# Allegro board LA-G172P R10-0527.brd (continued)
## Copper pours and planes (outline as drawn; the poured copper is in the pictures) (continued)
CPU_B+ on TOP: 99.74,37.64 100.38,37.01 102.28,37.01 102.36,36.93 102.36,36.73 102.48,36.6 104.49,36.6 104.72,36.37 105.33,36.37 105.48,36.22 105.48,35.46 105.38,35.36 104.79,35.36 104.69,35.46 104.69,35.69 104.24,36.14 100.38,36.14 100.15,35.91 100.15,35.56 99.99,35.41 98.09,35.41 98.08,35.39 97.97,35.39 97.89,35.3 97.89,33.78 97.58,33.48 97.58,30.48 97.48,30.38 94.66,30.38 94.53,30.25 94.53,28.88 94.61,28.8 97.35,28.8 97.77,28.38 99.85,28.38 100.38,27.86 100.4,27.89 102.13,27.89 102.31,27.71 102.31,27.56 102.46,27.41 104.49,27.41 104.72,27.18 105.33,27.18 105.35,27.15 105.35,26.42 105.33,26.39 104.79,26.39 104.21,26.97 100.43,26.97 100.17,26.72 100.17,26.34 100.05,26.21 98.01,26.21 97.89,26.08 97.89,24.56 97.73,24.41 97.73,21.56 97.58,21.41 94.36,21.41 93.77,21.99 93.77,24.8 92.22,26.35 92.22,37.82 92.54,38.14 97.03,38.14 97.52,37.64
CPU_B+ on VCC: 100.45,41.12 100.81,40.76 100.81,37.33 101.59,36.55 104.89,36.55 105.38,36.06 105.38,26.62 105.27,26.52 101.59,26.52 100.93,25.86 100.93,21.92 100.45,21.44 92.94,21.44 92.55,21.82 92.55,40.63 93.04,41.12
HPOUT-L on TOP (solid shape): 32.04,21.06 32.04,20.5 31.47,19.92 31.47,18.9 31.4,18.83 31.27,18.83 31.21,18.9 31.21,20.06 31.66,20.51 31.66,21.06 31.7,21.09 32,21.09
HPOUT-R on TOP (solid shape): 32.61,20.99 32.61,20.48 31.85,19.72 31.85,18.9 31.78,18.83 31.66,18.83 31.59,18.9 31.59,19.89 32.23,20.52 32.23,21.02 32.24,21.04 32.56,21.04
JUSBC1_GND on TOP (solid shape): 10.99,56.68 10.99,55.75 11.27,55.47 11.27,54.71 11.15,54.58 9.88,54.58 9.75,54.71 9.75,55.2 9.53,55.42 8.93,55.42 8.71,55.64 8.71,56.32 8.91,56.52 9.53,56.52 9.75,56.74 9.75,56.74 9.88,56.87 10.8,56.87
JUSBC1_GND on IN3 (solid shape): outline of 695 points within 1.24,55.73 11.15,69.7
JUSBC2_GND on TOP (solid shape): 288.01,67.14 288.01,65.06 287.75,64.81 285.47,64.81 285.41,64.86 285.41,66.74 285.97,67.3 287.84,67.3
JUSBC2_GND on IN3: 282.45,69.22 281.69,69.22 281.08,69.82 281.08,78.78 283.62,81.32 287,81.32 287.9,81.13 288.8,81.32 291.29,81.32 291.59,81.02 291.59,79.15 291.21,78.77 287.1,78.77 287.03,78.91 286.93,79.03 286.28,79.12 285.93,78.57 285.93,69.13 286.43,68.54 287.1,68.93 290.86,68.93 291.05,68.74 291.05,67.85 290.61,67.41 289.72,67.41 288.51,66.2 285.47,66.2
LX1_VCCIN on TOP (solid shape): 109.19,42.59 109.19,40.89 108.99,40.69 108.99,35.33 108.83,35.18 107.51,35.18 106.19,33.86 106.19,33.3 105.96,33.07 105.23,33.07 105.1,33.2 105.1,34.21 105.18,34.29 105.46,34.29 105.58,34.42 105.58,36.32 105.43,36.47 104.79,36.47 104.64,36.63 104.64,36.65 104.62,36.68 102.59,36.68 102.48,36.78 102.48,38.68 102.69,38.89 104.95,38.89 105.3,39.24 107.64,39.24 107.82,39.42 107.82,42.59 108,42.77 109.01,42.77
LX2_VCCIN on TOP (solid shape): 108.8,30.9 108.8,26.88 108.8,26.87 108.8,26.23 107.62,25.05 107.62,21.93 107.3,21.61 106.76,21.61 105.95,22.43 104.52,22.43 104.16,22.78 104.16,23.8 104.41,24.05 105.23,24.05 105.47,24.29 105.47,26.29 105.47,26.29 105.47,27.19 105.37,27.29 104.76,27.29 104.57,27.48 104.56,27.48 104.53,27.51 102.53,27.51 102.41,27.63 102.41,28 102.41,29.49 102.48,29.56 103.82,29.56 103.86,29.56 105.59,31.3 108.4,31.3
LX_0.6V on TOP: 78.18,71.65 78.26,71.74 79.95,71.74 80.18,71.51 80.18,69.37 80.72,68.83 81.66,68.83 81.76,68.73 81.76,68.53 81.71,68.48 80.03,68.48 79.47,67.92 79.47,66.58 79.41,66.52 78.9,66.52 78.84,66.58 78.84,67.18 78.65,67.37 78.34,67.37 78.18,67.53
LX_1.1V on TOP (solid shape): 101.7,64.13 101.7,62.61 102.09,62.22 102.09,59.84 101.94,59.69 98.19,59.69 97.68,60.2 97.68,60.2 97.61,60.27 95.26,60.27 95.11,60.42 95.11,61.28 95.22,61.39 97.48,61.39 98.58,62.49 99.66,62.49 99.71,62.55 99.71,63.22 99.82,63.32 100.45,63.32 100.6,63.47 100.6,64.11 100.65,64.16 101.67,64.16
LX_1.8V on TOP (solid shape): 208.99,25.6 208.99,23.93 209.37,23.54 209.37,21.92 209.52,21.77 209.91,21.77 209.96,21.71 210.61,21.71 210.66,21.66 210.66,21.46 210.64,21.44 210.14,21.44 210.06,21.36 208.93,21.36 207.85,20.28 207.31,20.28 207.11,20.07 207.11,19.16 207.02,19.08 206.39,19.08 206.22,19.25 206.22,20.51 205.94,20.79 205.94,23.86 206,23.93 207.92,23.93 208.08,24.09 208.08,25.59 208.12,25.62 208.96,25.62
LX_3V on TOP (solid shape): 81.76,57.5 81.76,56.64 81.83,56.56 81.83,55.04 82.15,54.72 82.15,53.86 82.67,53.34 83.24,53.34 84,52.58 85.41,52.58 85.57,52.42 85.57,50.7 85.49,50.62 84.48,50.62 82.97,49.11 80.07,49.11 79.84,49.35 79.84,55.08 80.46,55.7 80.49,55.7 80.59,55.8 80.59,56.08 81.15,56.64 81.21,56.64 81.24,56.67 81.27,56.67 81.38,56.77 81.38,56.8 81.39,56.81 81.39,57.52 81.43,57.55 81.71,57.55
LX_5V on TOP (solid shape): 22.7,7.47 23.59,7.47 23.72,7.34 23.72,7.21 23.55,7.05 23.04,7.05 22.96,6.97 21.32,6.97 20.67,6.32 20.67,3.53 20.54,3.4 19.97,3.4 19.78,3.21 19.78,2.51 19.72,2.45 18.19,2.45 18.13,2.51 18.13,4.29 17.75,4.67 16.23,4.67 15.97,4.93 15.97,7.53 16.32,7.88 18.92,7.88 19.34,8.29 21.88,8.29
LX_5VB on TOP (solid shape): 275.5,8.42 275.5,3.08 275.24,2.83 274.15,2.83 273.37,2.05 272.51,2.05 272.18,2.38 272.18,2.84 271.56,3.47 271.56,4.33 270.76,5.13 269.49,5.13 269.44,5.18 269.44,5.48 269.54,5.59 270.18,5.59 270.73,5.59 271.98,5.59 272,5.59 272.23,5.82 272.23,5.84 272.28,5.89 272.28,7.49 272.38,7.59 273.27,7.59 273.97,8.29 273.97,8.42 274.1,8.55 275.37,8.55
LX_AUX on TOP (solid shape): 147.58,12.79 147.58,7.66 146.46,6.54 146.46,4.32 146.32,4.17 145.74,4.17 145.51,4.4 145.51,6.66 145.24,6.93 144.5,6.93 144.44,6.98 144.44,7.73 144.44,7.73 144.44,9.23 144.13,9.55 142.06,9.55 141.9,9.7 141.9,10.84 142.06,11 144.13,11 144.37,11.24 144.37,13.28 144.56,13.47 146.91,13.47
LX_PWR2 on TOP: 195.97,9.03 197.09,9.03 197.24,8.88 197.24,8.7 197.14,8.6 195.49,8.6 195.09,8.2 195.09,7.64 194.77,7.33 194.77,6.46 194.72,6.41 194.24,6.41 192.41,6.41 192.23,6.23 192.23,5.25 192.17,5.18 191.65,5.18 191.6,5.23 191.6,13.23 191.88,13.51 193.14,13.51 193.38,13.26 193.38,11.14 193.56,10.96 194.26,10.26 194.74,10.26
LX_PWR3 on TOP: 216.59,32.33 218.6,32.33 219.51,33.25 219.81,33.25 220.17,33.61 220.17,34.18 220.33,34.34 221,34.34 221.14,34.2 221.14,32.29 221.08,32.23 220,32.23 218.98,31.22 218.98,29.36 218.83,29.21 217.53,29.21 216.85,28.52 216.85,27.96 216.67,27.79 216.54,27.79 216.39,27.94 216.39,30.1 216.38,30.11 216.38,30.26 215.96,30.68 215.96,31.65 215.25,32.36 215.25,32.59 214.84,32.99 214.41,32.99 214.23,33.17 214.23,33.76 214.29,33.81 215.11,33.81
MIC2-VREFO-R on TOP (solid shape): 31.16,21.91 31.16,21.23 30.93,21 30.93,20.39 30.65,20.12 30.65,18.91 30.58,18.83 30.49,18.83 30.42,18.9 30.42,20.27 30.6,20.45 30.6,21.54 30.51,21.63 30.13,21.63 30.07,21.69 30.07,22.07 30.13,22.13 30.94,22.13
Net_28 on BOTTOM (solid shape): outline of 196 points within 40.67,3.45 45.17,7.95
PANEL_PWRGD on BOTTOM (solid shape): 128.9,79.25 128.9,77.79 128.87,77.76 128,77.76 127.98,77.79 127.98,78.21 128.28,78.52 128.28,79.25 128.33,79.3 128.85,79.3
PANEL_PWRGD on BOTTOM (solid shape): 125.4,79.19 125.4,77.82 125.37,77.79 123.8,77.79 123.76,77.84 123.76,78.4 123.8,78.44 124.33,78.44 124.37,78.49 124.37,79.27 124.45,79.34 125.25,79.34
PANEL_PWRGD on IN3 (solid shape): 128.92,78.72 128.92,77.99 128.73,77.81 127.24,77.81 127.16,77.84 127.14,77.93 126.91,78.22 126.7,77.92 126.69,77.83 126.6,77.78 124.44,77.78 124.33,77.9 124.33,78.75 124.45,78.87 128.77,78.87
PD_L_DRAIN1 on TOP (solid shape): 16.33,17.09 16.33,17 16.24,16.91 16.15,16.91 15.43,17.63 15.26,17.63 14.54,16.91 14.54,16.64 15.21,15.97 15.21,15.88 15.12,15.79 14.94,15.79 12.56,18.17 12.29,18.17 11.62,17.49 11.53,17.49 11.44,17.58 11.44,17.67 13.5,19.74 13.68,19.74
PD_L_DRAIN1 on BOTTOM (solid shape): 15.34,17.98 15.34,17.72 14.42,16.8 13.78,16.8 12.37,18.21 12.37,18.5 13.49,19.63 13.69,19.63
PD_L_DRAIN1 on IN1 (solid shape): 15.34,17.98 15.34,17.72 14.26,16.64 13.94,16.64 12.37,18.21 12.37,18.5 13.49,19.63 13.69,19.63
PD_L_DRAIN1 on IN2 (solid shape): 15.34,17.98 15.34,17.72 14.26,16.64 13.94,16.64 12.37,18.21 12.37,18.5 13.49,19.63 13.69,19.63
PD_L_DRAIN1 on IN3 (solid shape): 15.34,17.98 15.34,17.72 14.26,16.64 13.94,16.64 12.37,18.21 12.37,18.5 13.49,19.63 13.69,19.63
PD_L_DRAIN2 on TOP (solid shape): 13.37,20.05 13.37,19.78 11.35,17.76 11.26,17.76 11.17,17.85 11.17,17.94 11.89,18.66 11.89,18.84 9.42,21.31 9.42,21.4 9.55,21.53 9.64,21.53 10.36,20.82 10.54,20.82 11.3,21.58 11.3,21.76 10.59,22.48 10.59,22.57 10.68,22.66 10.77,22.66
PD_L_DRAIN2 on BOTTOM (solid shape): 13.3,19.98 13.3,19.72 12.22,18.64 11.91,18.64 10.26,20.29 10.26,20.55 11.34,21.63 11.65,21.63
PD_L_DRAIN2 on IN1 (solid shape): 13.3,19.98 13.3,19.72 12.22,18.64 11.91,18.64 10.26,20.29 10.26,20.55 11.34,21.63 11.65,21.63
PD_L_DRAIN2 on IN2 (solid shape): 13.3,19.98 13.3,19.72 12.22,18.64 11.91,18.64 10.26,20.29 10.26,20.55 11.34,21.63 11.65,21.63
PD_L_DRAIN2 on IN3 (solid shape): 13.3,19.98 13.3,19.72 12.22,18.64 11.91,18.64 10.26,20.29 10.26,20.55 11.34,21.63 11.65,21.63
PD_R_DRAIN1 on BOTTOM (solid shape): 280.89,13.18 280.89,10.96 280.7,10.77 279.18,10.77 279.05,10.9 279.05,13.24 279.18,13.37 280.7,13.37
PD_R_DRAIN1 on IN1 (solid shape): 280.89,13.18 280.89,10.96 280.7,10.77 279.18,10.77 279.05,10.9 279.05,13.24 279.18,13.37 280.7,13.37
PD_R_DRAIN1 on IN2 (solid shape): 280.89,13.18 280.89,10.96 280.7,10.77 279.18,10.77 279.05,10.9 279.05,13.24 279.18,13.37 280.7,13.37
PD_R_DRAIN1 on IN3 (solid shape): 280.89,13.18 280.89,10.96 280.7,10.77 279.18,10.77 279.05,10.9 279.05,13.24 279.18,13.37 280.7,13.37
PD_R_DRAIN1 on TOP: 280.99,9.55 280.99,13.26 280.75,13.51 277.85,13.51 277.82,13.47 277.82,13.26 277.87,13.21 278.94,13.21 279.03,13.12 279.03,9.47 279.06,9.44 279.33,9.44 279.37,9.49 279.37,10.61 279.43,10.67 280.63,10.67 280.71,10.59 280.71,9.56 280.74,9.53 280.97,9.53
PD_R_DRAIN2 on TOP (solid shape): 279.37,17.52 279.37,16.47 279.43,16.41 280.63,16.41 280.68,16.45 280.68,17.51 280.72,17.55 280.91,17.55 280.96,17.5 280.96,13.72 280.87,13.63 277.87,13.63 277.8,13.71 277.8,13.85 277.85,13.91 278.92,13.91 279.06,14.05 279.06,17.5 279.13,17.57 279.32,17.57
PD_R_DRAIN2 on BOTTOM (solid shape): 280.89,16.17 280.89,13.82 280.7,13.63 279.24,13.63 279.05,13.82 279.05,16.17 279.18,16.29 280.77,16.29
PD_R_DRAIN2 on IN1 (solid shape): 279.79,16.21 280.85,16.21 280.89,16.17 280.89,13.82 280.7,13.63 279.24,13.63 279.05,13.82 279.05,16.17 279.18,16.29 279.7,16.29
PD_R_DRAIN2 on IN2 (solid shape): 280.89,16.17 280.89,13.82 280.7,13.63 279.24,13.63 279.05,13.82 279.05,16.17 279.18,16.29 280.77,16.29
PD_R_DRAIN2 on IN3 (solid shape): 280.89,16.17 280.89,13.82 280.7,13.63 279.24,13.63 279.05,13.82 279.05,16.17 279.18,16.29 280.77,16.29
PWM2 on TOP (solid shape): 101.24,26.8 101.24,25.22 101.09,25.07 100.61,25.07 100.43,25.26 100.43,26.72 100.53,26.82 101.21,26.82
RING2 on TOP (solid shape): 30.49,21.33 30.49,20.52 30.26,20.29 30.26,18.9 30.2,18.83 30.07,18.83 30.03,18.87 30.03,21.31 30.16,21.44 30.39,21.44
RING2 on BOTTOM (solid shape): 9.5,75.91 9.5,75.06 9.44,75 8.4,75 8.28,75.13 8.28,75.93 8.32,75.97 9.44,75.97
RING2 on BOTTOM (solid shape): 31.08,21.25 31.08,20.99 31.02,20.93 30.89,20.93 30.33,20.37 30.16,20.37 30.03,20.5 30.03,21.3 30.17,21.44 30.89,21.44
RING2 on IN3 (solid shape): 9.94,75.4 9.94,74.56 9.7,74.31 9.06,74.31 8.51,74.86 8.51,75.88 8.64,76 9.34,76
RING2 on IN3 (solid shape): 30.84,22.27 30.84,20.53 30.69,20.38 30.16,20.38 30.03,20.51 30.03,21.64 29.79,21.88 29.79,22.03 30.31,22.55 30.56,22.55
RING2_CONN on IN1 (solid shape): 8.62,72.84 8.72,72.84 8.84,72.72 8.84,71.98 8.71,71.85 7.61,71.85 7.52,71.95 7.52,72.77 7.59,72.84 8.61,72.84
RING2_CONN on IN3 (solid shape): 8.92,72.82 8.92,71.92 8.72,71.72 7.61,71.72 7.51,71.81 7.51,72.94 7.58,73.01 8.73,73.01
RING2_CONN on BOTTOM: 8.32,74.29 8.32,74.7 8.35,74.73 8.86,74.73 8.93,74.67 8.93,73.88 9.39,73.42 9.39,72.82 8.94,72.36 6.54,72.36 5.17,73.73 5.17,74.5 5.23,74.56 5.82,74.56 6.77,73.61 7.45,73.61 7.63,73.78 7.63,74.09 7.99,74.09 8.09,74.19 8.22,74.19
SD_REG2 on TOP (solid shape): 283.88,28.88 283.88,28.45 283.87,28.44 283.32,28.44 282.82,27.94 281.65,27.94 281.61,27.99 281.61,28.24 281.63,28.3 281.63,28.35 281.63,28.44 281.74,28.55 282.49,28.55 282.87,28.93 283.05,28.93 283.26,28.85 283.47,28.93 283.83,28.93
SLEEVE on TOP (solid shape): 29.88,22.08 29.88,18.9 29.81,18.83 29.69,18.83 29.62,18.9 29.62,20.29 29.37,20.55 29.37,22.07 29.43,22.13 29.83,22.13
SLEEVE on BOTTOM (solid shape): 14.73,72.14 14.73,70.18 14.38,69.83 12.15,69.83 11.95,70.02 11.95,70.75 12.1,70.89 13.57,70.89 13.73,71.05 13.73,71.47 11.15,74.04 11.12,74.07 11.12,74.08 11.33,74.29 11.34,74.28 11.71,74.28 12.14,74.71 12.16,74.71
SLEEVE on IN2 (solid shape): 14.13,70.71 14.13,70.01 13.97,69.85 12.13,69.85 12,69.98 12,70.81 12.13,70.93 13.91,70.93
SLEEVE on IN2 (solid shape): 29.18,21.44 29.75,21.44 29.88,21.31 29.88,20.48 29.75,20.36 28.73,20.36 28.16,20.93 28.16,21.18 28.61,21.63 28.99,21.63
SLEEVE_CONN on BOTTOM (solid shape): 11.97,74.91 11.97,74.9 11.6,74.53 11.45,74.53 11.01,74.97 10.97,74.97 10.52,74.51 10.52,74.46 10.83,74.14 10.83,71.56 10.75,71.48 9.9,71.48 9.78,71.6 9.78,75.17 9.81,75.2 10.41,75.2 10.96,75.75 11.12,75.75
SLEEVE_CONN on IN3 (solid shape): 11.27,72.3 11.27,71.52 11.16,71.41 9.94,71.41 9.81,71.54 9.81,72.36 9.94,72.49 11.08,72.49
SLEEVE_CONN on IN1: 9.87,71.84 9.87,72.67 9.99,72.79 11.07,72.79 11.2,72.67 11.2,71.84 11.07,71.71 9.99,71.71
SNUB_CHG2 on TOP: 73.95,42.96 74.16,42.75 74.92,42.75 75.03,42.65 75.03,41.63 74.96,41.57 73.44,41.57 73.31,41.69 73.31,44.62 73.41,44.72 73.84,44.72 73.95,44.62
SPK_-OUT-L+ on BOTTOM (solid shape): 28.85,16.5 28.85,15.85 28.76,15.76 27.93,15.76 27.83,15.86 27.83,16.6 28.04,16.8 28.54,16.8
SPK_-OUT-L- on BOTTOM (solid shape): 27.4,16.04 27.4,15.28 27.27,15.15 26.51,15.15 26.39,15.28 26.39,15.92 26.69,16.23 27.21,16.23
SPK_-OUT-R+ on BOTTOM (solid shape): 24.76,15.77 24.76,15.21 24.38,14.83 23.59,14.83 23.43,15 23.43,15.7 23.58,15.85 24.19,15.85 24.3,15.96 24.57,15.96
SPK_-OUT-R+ on IN1 (solid shape): 25.5,15.91 25.5,15.59 25.69,15.4 26.32,15.4 26.39,15.34 26.39,14.9 26.26,14.77 25.24,14.77 24.54,15.47 24.54,15.91 24.67,16.04 25.37,16.04
SPK_-OUT-R- on BOTTOM (solid shape): 23.48,16.93 25.64,16.93 25.71,16.85 26.31,16.85 26.45,16.71 26.45,16.37 26.21,16.13 25.45,16.13 25.36,16.22 24.18,16.22 24.07,16.11 22.76,16.11 22.64,16.23 22.64,16.99 22.77,17.12 23.29,17.12
SPK_L+ on TOP (solid shape): 13.37,5.95 13.37,3.28 13.25,3.15 12.87,3.15 12.74,3.28 12.74,6.01 12.87,6.14 13.18,6.14
SPK_L+ on BOTTOM (solid shape): 13.82,7.67 13.82,6.12 13.9,6.04 13.9,3.48 13.56,3.15 12.93,3.15 12.74,3.34 12.74,4.17 13.18,4.61 13.18,6.91 13.01,7.09 13.01,7.71 13.04,7.73 13.76,7.73
SPK_L- on TOP (solid shape): 12.49,6.07 12.49,3.28 12.36,3.15 12.04,3.15 11.91,3.28 11.91,6.01 12.04,6.14 12.42,6.14
SPK_L- on BOTTOM (solid shape): 12.09,7.64 12.09,6.07 12.18,5.98 12.18,5.09 12.43,4.84 12.43,3.29 12.29,3.15 11.66,3.15 11.53,3.28 11.53,5.05 11.47,5.11 11.47,6.85 11.22,7.1 11.22,7.69 11.26,7.73 12,7.73
SPK_R+ on TOP (solid shape): 11.66,6.07 11.66,3.79 11.02,3.15 10.64,3.15 10.52,3.28 10.52,4.04 11.15,4.68 11.15,6.01 11.28,6.14 11.6,6.14
SPK_R+ on BOTTOM (solid shape): 10.38,7.63 10.38,6.24 10.47,6.16 10.47,5.05 11.22,4.31 11.22,3.34 10.95,3.08 10.13,3.08 10.05,3.16 10.05,4.51 9.69,4.87 9.69,6.95 9.56,7.09 9.56,7.7 9.58,7.72 10.29,7.72
SPK_R- on TOP (solid shape): 10.87,6.04 10.87,4.77 10.2,4.11 10.2,3.41 9.95,3.15 9.32,3.15 9.18,3.29 9.18,4.04 10.33,5.18 10.33,5.95 10.49,6.11 10.8,6.11
SPK_R- on BOTTOM (solid shape): 8.56,7.67 8.56,6.22 8.74,6.04 8.74,5.82 8.74,5.82 8.74,5.1 9.73,4.11 9.73,3.26 9.62,3.15 8.55,3.15 7.54,4.16 7.54,7.67 7.61,7.73 8.49,7.73
TS_EN_R on TOP: 174.71,67.23 174.71,66.22 175.18,65.76 176.15,65.76 176.2,65.7 176.2,65.22 176.18,65.2 173.91,65.2 173.88,65.23 173.88,65.61 174.42,66.15 174.42,67.23 174.48,67.29 174.65,67.29
N30258320 on TOP: 77.38,18.77 78.26,18.77 78.46,18.96 78.46,19.59 78.33,19.72 77.88,19.72 77.5,20.1 77.5,21.87 77.46,21.91 76.46,21.91 76.36,21.81 76.36,19.98 77.25,19.09 77.25,18.9
N52032474 on TOP: 213.98,20.53 211.49,20.53 211.3,20.72 210.2,20.72 210,20.93 210,21.16 210.18,21.33 210.69,21.33 211.14,21.79 211.3,21.79 212.06,22.55 214.73,22.55 214.85,22.43 214.85,21.89 215.51,21.23 215.51,20.19 215.44,20.12 214.4,20.12
N52752182 on TOP: 207.32,18.88 207.42,18.77 208.19,18.77 208.27,18.68 208.27,17.95 208.27,17.93 208.22,17.88 207.34,17.88 207.07,18.14 206.48,18.14 206.4,18.23 206.4,18.77 206.51,18.88
N52761358 on TOP: 143.1,15.26 143.1,14.5 143.33,14.27 144.01,14.27 144.37,13.92 144.37,13.77 144.44,13.69 145.08,13.69 145.18,13.79 145.18,15.14 144.96,15.37 143.2,15.37
N52765760 on TOP (solid shape): 106.45,43.08 106.45,40.92 105.33,40.92 105.25,40.99 105.25,41.86 104.79,42.31 104.79,42.33 104.12,42.33 104.06,42.39 104.06,43.1 104.13,43.18 106.34,43.18
N52768296 on TOP (solid shape): 109.62,24.18 109.62,23.89 110.19,23.32 110.82,23.32 110.85,23.29 110.85,22.49 110.73,22.38 108.48,22.38 108.3,22.55 108.3,24.15 108.43,24.28 109.52,24.28
N52905683 on IN2 (solid shape): 95.47,66.14 95.47,55.79 94.91,55.23 93.96,55.23 93.47,55.73 93.47,57.19 93.47,57.2 93.49,57.31 93.47,57.43 93.47,57.44 93.47,59.73 93.47,59.74 93.49,59.85 93.47,59.97 93.47,59.98 93.47,62.27 93.47,62.28 93.49,62.39 93.47,62.51 93.47,62.52 93.47,62.78 94.35,63.47 93.47,64.17 93.47,66.04 93.7,66.27 95.35,66.27
N52905683 on TOP: 96.08,58.29 96.08,54.18 95.85,53.95 93.59,53.95 93.47,54.08 93.47,58.15 93.71,58.39 94.33,58.39 94.33,58.39 94.94,58.39 95.25,58.7 95.25,59.95 95.37,60.08 95.61,60.08 95.74,59.95 95.74,58.63
N52905683 on TOP: 95.32,61.49 95.17,61.64 95.17,62.91 94.56,63.52 94.56,66.52 94.57,66.53 94.57,66.96 95.31,67.7 96.08,67.7 96.14,67.64 96.14,63.51 95.76,63.12 95.76,61.62 95.63,61.49
N52924590 on TOP: 81.38,67.84 82.42,67.84 83.2,67.05 85.21,67.05 85.34,66.93 85.34,66.43 85.41,66.37 86.57,66.37 86.67,66.47 86.67,68.69 86.49,68.88 82.32,68.88 81.78,68.35 81.33,68.35 81.2,68.22 81.2,68.02
N52929367 on TOP: 102.48,62.48 102.31,62.66 102.31,65.41 102.42,65.52 103.29,65.52 103.47,65.34 103.47,63.77 103.67,63.56 104.29,63.56 104.4,63.45 104.4,62.82 104.07,62.48
N52994087 on TOP: 219.17,29.56 220.57,29.56 220.76,29.37 221.3,29.37 221.48,29.55 221.48,31.18 221.19,31.47 219.74,31.47 219.62,31.34 219.62,30.83 219.11,30.33 219.11,29.63
N52994160 on TOP: 216.29,28.52 216.29,27.91 216.78,27.42 216.77,27.41 216.77,21.77 216.57,21.56 215.62,21.56 215.07,22.11 215.07,25.6 214.54,26.14 214.54,27 214.64,27.1 215.5,27.1 215.65,27.25 215.65,28.34 215.86,28.55 216.26,28.55
N52994210 on TOP: 217.71,27.07 217.71,26.67 218.85,26.67 219.21,26.3 219.74,26.3 219.78,26.34 219.78,27.01 219.71,27.07
N52994410 on TOP (solid shape): 214.03,33.69 214.03,33.06 214.22,32.87 214.73,32.87 214.79,32.8 214.79,32.17 214.73,32.1 213.84,32.1 213.77,32.17 213.77,32.68 213.39,33.06 213.39,33.69 213.46,33.76 213.96,33.76
N53109404 on TOP: 98.62,64.77 100.07,64.77 100.48,64.36 100.48,63.52 100.43,63.47 99.74,63.47 99.66,63.55 99.66,63.83 99.54,63.96 98.62,63.96 98.52,64.06 98.52,64.67
N53177904 on TOP: 145.16,6.7 144.47,6.7 143.86,6.09 143.3,6.09 143.2,5.99 143.2,5.31 143.28,5.23 143.85,5.23 143.85,4.38 143.96,4.28 144.65,4.28 144.72,4.35 144.72,5.48 145.26,6.02 145.26,6.6
N53198392 on TOP: 81.86,56.72 81.83,56.74 81.83,57.5 81.5,57.83 81.5,59.26 81.33,59.43 81.33,63.78 81.55,64.01 83.59,64.01 83.77,63.82 83.77,61.07 83.81,61.07 83.81,61.03 83.61,60.83 83.36,60.83 83.23,60.7 83.23,59.61 82.44,58.82 82.44,56.95 82.21,56.72
N53198810 on TOP: 83.81,54.58 83.81,52.91 83.89,52.83 84.68,52.83 84.75,52.91 84.75,54.61 84.73,54.63 83.87,54.63
N53201443 on TOP (solid shape): 30,8.42 30,5.24 30.32,4.93 30.32,2.45 30,2.13 27.08,2.13 26.98,2.23 26.98,2.63 27.75,3.4 27.75,5.59 27.66,5.69 25.37,5.69 24.73,6.32 23.08,6.32 22.96,6.45 22.96,6.83 23,6.87 23.01,6.87 23.08,6.95 23.38,6.95 23.6,6.95 23.61,6.96 23.72,6.96 24.23,7.47 28.04,7.47 28.42,7.85 28.42,8.36 28.67,8.61 29.81,8.61
N53201891 on TOP (solid shape): 18,3.97 18,2.64 17.81,2.45 17.05,2.45 16.92,2.58 16.92,2.83 16.73,3.02 15.84,3.02 15.75,3.12 15.75,3.88 15.81,3.94 16.51,3.94 16.73,4.16 17.81,4.16
N53202040 on TOP (solid shape): 265.67,7.26 267.41,7.26 267.84,6.83 268.14,6.83 268.32,6.65 268.32,6.35 268.37,6.3 270.12,6.3 270.2,6.22 270.2,5.79 270.12,5.71 269.39,5.71 268.9,5.23 267.71,5.23 267.41,4.93 265.02,4.93 264.74,4.65 264.74,2.41 264.64,2.31 262.45,2.31 262.15,2.61 262.15,5.05 262.71,5.61 262.71,8.95 262.8,9.04 263.89,9.04
N53202478 on TOP (solid shape): 275.56,10.13 275.56,9.31 275.37,9.12 274.35,9.12 273.84,8.61 273.02,8.61 272.89,8.74 272.89,9.37 273.15,9.63 273.59,9.63 274.16,10.2 275.5,10.2
N53437419 on BOTTOM: 112.81,16.17 124.68,16.17 124.72,16.2 124.72,17.21 124.3,17.63 121.06,17.63 120.29,16.85 112.85,16.85 112.75,16.76 112.75,16.22
N55957128 on TOP: 23.6,23.32 24.91,23.32 25.13,23.11 25.13,21.7 24.66,21.23 24.66,20.35 24.62,20.31 23.6,20.31 23.51,20.41 23.51,23.23
N57317701 on TOP: 197.92,8.01 196.65,8.01 196.55,8.11 196.55,8.34 196.68,8.47 197.49,8.47 198.64,9.61 202.04,9.61 202.31,9.34 202.31,7.69 202.22,7.59 198.35,7.59
N57317772 on TOP (solid shape): 195.88,13.37 195.88,12.3 195.87,12.29 195.87,11.4 195.8,11.34 195.1,11.34 195.1,11.34 194.91,11.14 194.91,10.86 194.85,10.8 193.99,10.8 193.9,10.88 193.9,13.29 194.1,13.49 195.76,13.49
N57317853 on TOP: 194.08,5.27 194.02,5.21 192.57,5.21 192.5,5.27 192.5,5.84 192.55,5.89 193.29,5.89 193.32,5.92 193.32,6.12 193.38,6.17 194.05,6.17 194.07,6.15 194.07,5.27
N57581670 on TOP (solid shape): 78.52,67.16 78.52,66.33 78.71,66.14 78.71,65.31 78.65,65.25 78.01,65.25 77.95,65.31 77.95,67.16 78.01,67.22 78.46,67.22
N57652767 on TOP: 95.79,12.5 94.69,12.5 94.59,12.6 94.02,12.6 93.97,12.65 93.97,14.06 94.13,14.22 95.37,14.22 95.91,13.67 95.91,12.63
N58555592 on BOTTOM (solid shape): 124.39,81.84 124.39,79.8 124.14,79.55 122.56,79.55 122.49,79.63 122.49,81.17 123.26,81.95 124.28,81.95
N59636611 on TOP: 180.51,17.72 180.56,17.67 180.56,15.44 180.11,14.99 178.88,14.99 178.02,14.13 176.56,14.13 176.37,14.32 176.37,15.09 176.63,15.34 177.19,15.34 177.7,15.85 177.7,17.51 177.92,17.72
N60250631 on TOP (solid shape): 68.83,20.31 68.83,19.53 68.57,19.28 67.91,19.28 67.79,19.15 67.79,18.77 67.72,18.71 67.22,18.71 67.09,18.58 67.09,18.2 67.03,18.13 66.71,18.13 66.64,18.2 66.64,19.98 67.03,20.36 68.78,20.36
N73891446 on TOP: 87.2,63.57 86.95,63.82 86.95,64.31 87.04,64.4 87.48,64.4 87.91,64.83 87.91,65.89 88.31,66.28 88.31,67.5 88.8,67.99 89.53,67.99 89.61,67.91 89.61,65.99 89.41,65.79 88.98,65.79 88.83,65.65 88.83,64.13 88.28,63.57

Small or netless copper shapes (teardrops, artwork), in the pictures only: 150 on TOP, 40 on BOTTOM, 14 on IN1, 17 on IN3

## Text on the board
Ref Des/Silkscreen Bottom: H24 | S5 | H26 | H23 | H13 | H16 | H22 | H5 | S6 | H25 | Dell Innovation Excellence Platform
User.Comments: LAG172P | 2020-05-27 | 2019-05-27 | DDP31 | Sunny | 1.0(A00)
Ref Des/Silkscreen Top: S1 | S2 | H15 | H44 | H14 | A | S3 | S4 | DELL designed
GND4: GND4
XSECTION_CHART: * | L1: TOP | L2: GND1 | L3: IN1 | L4: GND2 | L5: VCC | L6: IN2 | L7: GND3 | L8: IN3 | L9: GND4 | L10: BOTTOM | DESIGN CROSS SECTION CHART | ___________________________ | TOTAL THICKNESS 33.95 MIL | 1-10 | 1-4 | 1-2 | 1-3 | 2-4 | 2-3 | 3-8 | 7-10 | 7-9 | 7-8 | 8-10 | 8-9 | 9-10
User.41: trace Width | Width/space | 3.9 | 4 / 4 | 3.6 / 4.4 | 3.2 / 4.6 | 2.4 / 5.6 | 2.6 / 5.4 | 11.7 | L8 | 40 ohm | 75 ohm | 50 ohm | Ref
User.42: FIGURE | SIZE | 8.0 | 75.0 | 79.0 | 94.0 | 102.0 | 114.0 | 26.0 | 40.0 | 43.0 | 51.0 | 43.0x20.0 | 51.0x28.0 | 63.0x28.0 | 75.0x28.0 | 79.0x28.0 | 87.0x16.0 | 91.0x20.0 | 217.0x98.0 | DRILL CHART: TOP to BOTTOM | ALL UNITS ARE IN MILS | TOLERANCE | +3.0/-3.0 | +2.0/-2.0 | PLATED | NON-PLATED | QTY | 2701 | 5 | 10 | 6 | 3 | 1 | 4 | 2
User.43: FIGURE | SIZE | 4.0 | DRILL CHART: TOP to IN1 | ALL UNITS ARE IN MILS | TOLERANCE | +1.0/-1.0 | PLATED | QTY | 2287
User.44: FIGURE | SIZE | 4.0 | DRILL CHART: TOP to GND2 | ALL UNITS ARE IN MILS | TOLERANCE | +1.0/-1.0 | PLATED | QTY | 3342
User.45: stack-up setting ok | FIGURE | SIZE | 4.0 | DRILL CHART: GND1 to IN1 | ALL UNITS ARE IN MILS | DRILL CHART: IN3 to GND4 | TOLERANCE | +1.0/-1.0 | PLATED | QTY | 415 | 8.0 | DRILL CHART: TOP to GND1 | DRILL CHART: GND1 to GND2 | DRILL CHART: IN1 to IN3 | +3.0/-3.0 | 1688 | 1103 | 2397 | DRILL CHART: GND3 to IN3 | DRILL CHART: GND3 to GND4 | DRILL CHART: GND3 to BOTTOM | DRILL CHART: IN3 to BOTTOM | DRILL CHART: GND4 to BOTTOM | 47 | 1348 | 1615 | 606 | 1698
